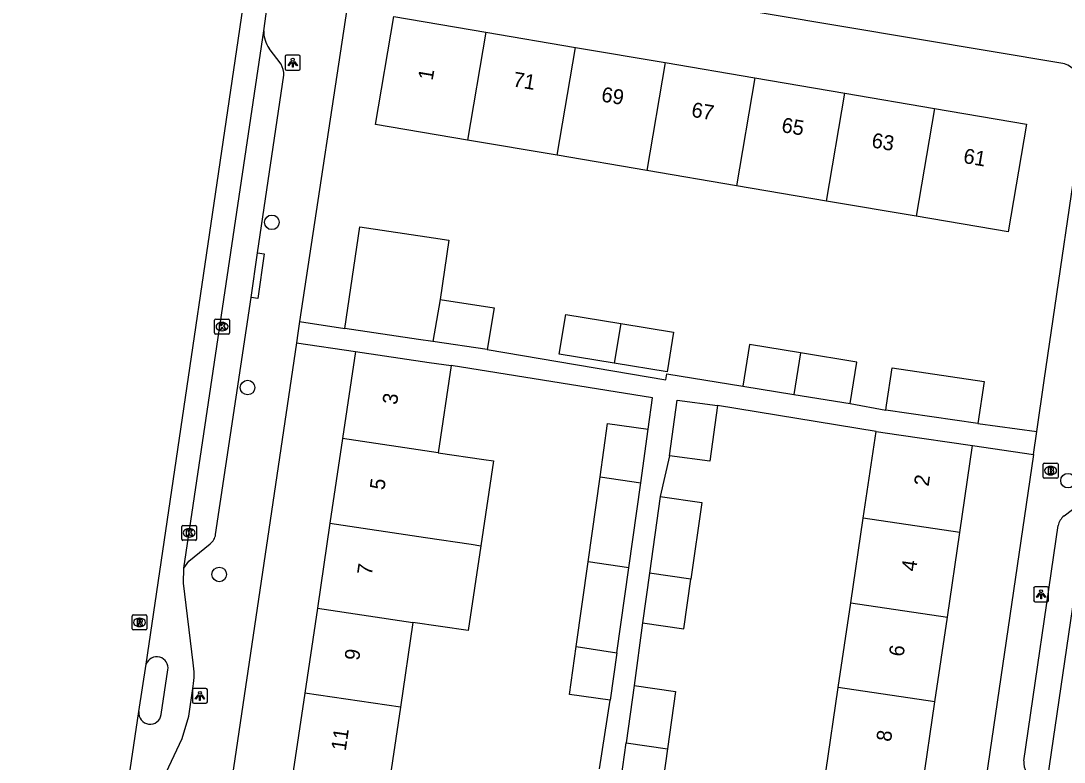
# Model space of a CAD drawing. Extents: x 163686 to 164493, y 382719 to 383870.
# Drawn here: x 163726.2 to 163796.1, y 383096.3 to 383145.9 of the extents above; entities that cross this region are included whole.
import ezdxf

# ---------------------------------------------------------------- set-up
doc = ezdxf.new("R2010")
doc.units = 0
for name, color, linetype in [('IMGEO_Boom', 7, 'Continuous'), ('IMGEO_Brandkraan', 7, 'Continuous'), ('IMGEO_Kolk', 7, 'Continuous'), ('IMGEO_Lichtpunt', 7, 'Continuous'), ('IMGEO_Pand', 7, 'Continuous'), ('IMGEO_Pand_nummerreeks', 7, 'Continuous'), ('IMGEO_Rijbaan_lokaal_open', 7, 'Continuous'), ('IMGEO_Rioolput', 7, 'Continuous'), ('IMGEO_Voetpad_open', 7, 'Continuous')]:
    doc.layers.add(name, color=color, linetype=linetype)

msp = doc.modelspace()

# ---------------------------------------------------------------- linework, layer by layer
at = {"layer": 'IMGEO_Boom'}
for centre in [(163743.043, 383132.436), (163741.413, 383121.365), (163796.388, 383115.13), (163739.516, 383108.846)]:
    msp.add_circle(centre, 0.489, dxfattribs=at)
at = {"layer": 'IMGEO_Brandkraan'}
for p, q in [((163794.721, 383115.373), (163794.721, 383116.225)), ((163794.796, 383116.299), (163795.648, 383116.299)), ((163795.722, 383116.225), (163795.722, 383115.373)), ((163795.232, 383115.519), (163795.207, 383115.519)), ((163795.209, 383116.079), (163795.234, 383116.079)), ((163795.648, 383115.299), (163794.796, 383115.299))]:
    msp.add_line(p, q, dxfattribs=at)
for points in [[(163794.721, 383115.373), (163794.721, 383116.225)], [(163794.796, 383116.299), (163795.648, 383116.299)], [(163795.722, 383116.225), (163795.722, 383115.373)], [(163795.069, 383115.999), (163795.069, 383115.599), (163795.282, 383115.599)], [(163795.3, 383115.999), (163795.069, 383115.999)], [(163795.248, 383115.918), (163795.194, 383115.918), (163795.194, 383115.842)], [(163795.194, 383115.842), (163795.247, 383115.842)], [(163795.256, 383115.766), (163795.194, 383115.766), (163795.194, 383115.685)], [(163795.194, 383115.685), (163795.256, 383115.685)], [(163795.648, 383115.299), (163794.796, 383115.299)]]:
    msp.add_lwpolyline(points, dxfattribs=at)
for centre, radius, start, end in [((163794.798, 383116.223), 0.0765, 91.55205, 178.44795), ((163794.798, 383116.223), 0.0765, 91.55205, 178.44795), ((163795.646, 383116.223), 0.0765, 1.55205, 88.44795), ((163795.646, 383116.223), 0.0765, 1.55205, 88.44795), ((163795.249, 383115.88), 0.0379, 267.82845, 90.93552), ((163795.257, 383115.725), 0.0404, 269.87594, 90.50774), ((163795.288, 383115.85), 0.251, 268.66757, 293.53466), ((163795.304, 383115.854), 0.145, 59.4692, 91.53667), ((163795.329, 383115.901), 0.0922, 285.51372, 58.15012), ((163795.334, 383115.709), 0.105, 301.31148, 78.98903), ((163794.798, 383115.375), 0.0765, 181.55205, 268.44795), ((163794.798, 383115.375), 0.0765, 181.55205, 268.44795), ((163795.646, 383115.375), 0.0765, 271.55205, 358.44795), ((163795.646, 383115.375), 0.0765, 271.55205, 358.44795)]:
    msp.add_arc(centre, radius, start, end, dxfattribs=at)
for centre, major_axis, ratio, start_param, end_param in [((163795.208, 383115.799), (-0.387, 0.002), 0.722429, 4.712389, 7.853982), ((163795.233, 383115.799), (-0.39, 0.002), 0.717154, 1.570796, 4.712389)]:
    msp.add_ellipse(centre, major_axis=major_axis, ratio=ratio, start_param=start_param, end_param=end_param, dxfattribs=at)
at = {"layer": 'IMGEO_Kolk'}
for p, q in [((163739.209, 383125.023), (163739.209, 383125.875)), ((163739.284, 383125.949), (163740.136, 383125.949)), ((163740.21, 383125.875), (163740.21, 383125.023)), ((163739.697, 383125.729), (163739.722, 383125.729)), ((163740.136, 383124.949), (163739.284, 383124.949)), ((163739.72, 383125.169), (163739.695, 383125.169)), ((163737.002, 383111.206), (163737.002, 383112.058)), ((163737.077, 383112.132), (163737.929, 383112.132)), ((163737.49, 383111.912), (163737.515, 383111.912)), ((163738.003, 383112.058), (163738.003, 383111.206)), ((163737.513, 383111.352), (163737.488, 383111.352)), ((163737.929, 383111.132), (163737.077, 383111.132))]:
    msp.add_line(p, q, dxfattribs=at)
for points in [[(163739.209, 383125.023), (163739.209, 383125.875)], [(163739.284, 383125.949), (163740.136, 383125.949)], [(163740.21, 383125.875), (163740.21, 383125.023)], [(163739.53, 383125.649), (163739.653, 383125.649), (163739.653, 383125.498), (163739.783, 383125.649), (163739.947, 383125.649), (163739.801, 383125.498), (163739.954, 383125.249), (163739.802, 383125.249), (163739.717, 383125.413), (163739.653, 383125.346), (163739.653, 383125.249), (163739.53, 383125.249), (163739.53, 383125.649)], [(163740.136, 383124.949), (163739.284, 383124.949)], [(163737.002, 383111.206), (163737.002, 383112.058)], [(163737.077, 383112.132), (163737.929, 383112.132)], [(163738.003, 383112.058), (163738.003, 383111.206)], [(163737.323, 383111.832), (163737.446, 383111.832), (163737.446, 383111.681), (163737.576, 383111.832), (163737.74, 383111.832), (163737.594, 383111.681), (163737.747, 383111.432), (163737.595, 383111.432), (163737.51, 383111.596), (163737.446, 383111.529), (163737.446, 383111.432), (163737.323, 383111.432), (163737.323, 383111.832)], [(163737.929, 383111.132), (163737.077, 383111.132)]]:
    msp.add_lwpolyline(points, dxfattribs=at)
for centre, start, end in [((163739.286, 383125.873), 91.55205, 178.44795), ((163739.286, 383125.873), 91.55205, 178.44795), ((163740.134, 383125.873), 1.55205, 88.44795), ((163740.134, 383125.873), 1.55205, 88.44795), ((163739.286, 383125.025), 181.55205, 268.44795), ((163739.286, 383125.025), 181.55205, 268.44795), ((163740.134, 383125.025), 271.55205, 358.44795), ((163740.134, 383125.025), 271.55205, 358.44795), ((163737.079, 383112.056), 91.55205, 178.44795), ((163737.079, 383112.056), 91.55205, 178.44795), ((163737.927, 383112.056), 1.55205, 88.44795), ((163737.927, 383112.056), 1.55205, 88.44795), ((163737.079, 383111.208), 181.55205, 268.44795), ((163737.079, 383111.208), 181.55205, 268.44795), ((163737.927, 383111.208), 271.55205, 358.44795), ((163737.927, 383111.208), 271.55205, 358.44795)]:
    msp.add_arc(centre, 0.0765, start, end, dxfattribs=at)
for centre, major_axis, ratio, start_param, end_param in [((163739.696, 383125.449), (-0.387, 0.002), 0.722429, 4.712389, 7.853982), ((163739.721, 383125.449), (-0.39, 0.002), 0.717154, 1.570796, 4.712389), ((163737.489, 383111.632), (-0.387, 0.002), 0.722429, 4.712389, 7.853982), ((163737.514, 383111.632), (-0.39, 0.002), 0.717154, 1.570796, 4.712389)]:
    msp.add_ellipse(centre, major_axis=major_axis, ratio=ratio, start_param=start_param, end_param=end_param, dxfattribs=at)
at = {"layer": 'IMGEO_Lichtpunt'}
for p, q in [((163743.941, 383143.537), (163743.941, 383142.73)), ((163743.941, 383143.537), (163743.941, 383142.73)), ((163744.843, 383143.632), (163744.035, 383143.632)), ((163744.843, 383143.632), (163744.035, 383143.632)), ((163744.937, 383142.73), (163744.937, 383143.537)), ((163744.937, 383142.73), (163744.937, 383143.537)), ((163744.035, 383142.636), (163744.843, 383142.636)), ((163744.035, 383142.636), (163744.843, 383142.636)), ((163794.088, 383107.922), (163794.088, 383107.115)), ((163794.088, 383107.922), (163794.088, 383107.115)), ((163794.99, 383108.017), (163794.182, 383108.017)), ((163794.99, 383108.017), (163794.182, 383108.017)), ((163795.084, 383107.115), (163795.084, 383107.922)), ((163795.084, 383107.115), (163795.084, 383107.922)), ((163794.182, 383107.021), (163794.99, 383107.021)), ((163794.182, 383107.021), (163794.99, 383107.021)), ((163737.726, 383101.118), (163737.726, 383100.311)), ((163737.726, 383101.118), (163737.726, 383100.311)), ((163738.628, 383101.213), (163737.82, 383101.213)), ((163738.628, 383101.213), (163737.82, 383101.213)), ((163738.722, 383100.311), (163738.722, 383101.118)), ((163738.722, 383100.311), (163738.722, 383101.118)), ((163737.82, 383100.217), (163738.628, 383100.217)), ((163737.82, 383100.217), (163738.628, 383100.217))]:
    msp.add_line(p, q, dxfattribs=at)
for points in [[(163744.315, 383143.201), (163744.354, 383143.173), (163744.166, 383142.911), (163744.128, 383142.938), (163744.315, 383143.201)], [(163744.417, 383143.153), (163744.464, 383143.153), (163744.464, 383142.831), (163744.417, 383142.831), (163744.417, 383143.153)], [(163744.527, 383143.173), (163744.565, 383143.2), (163744.752, 383142.938), (163744.713, 383142.91), (163744.527, 383143.173)], [(163794.462, 383107.586), (163794.501, 383107.558), (163794.313, 383107.296), (163794.275, 383107.323), (163794.462, 383107.586)], [(163794.564, 383107.538), (163794.611, 383107.538), (163794.611, 383107.216), (163794.564, 383107.216), (163794.564, 383107.538)], [(163794.674, 383107.558), (163794.712, 383107.585), (163794.899, 383107.323), (163794.86, 383107.295), (163794.674, 383107.558)], [(163738.1, 383100.782), (163738.139, 383100.754), (163737.951, 383100.492), (163737.913, 383100.519), (163738.1, 383100.782)], [(163738.202, 383100.734), (163738.249, 383100.734), (163738.249, 383100.412), (163738.202, 383100.412), (163738.202, 383100.734)], [(163738.312, 383100.754), (163738.35, 383100.781), (163738.537, 383100.519), (163738.498, 383100.491), (163738.312, 383100.754)]]:
    msp.add_lwpolyline(points, dxfattribs=at)
for centre in [(163744.44, 383143.335), (163794.587, 383107.72), (163738.225, 383100.916)]:
    msp.add_circle(centre, 0.0994, dxfattribs=at)
for centre, start, end in [((163744.035, 383143.537), 90, 180), ((163744.035, 383143.537), 90, 180), ((163744.843, 383143.537), 0, 90), ((163744.843, 383143.537), 0, 90), ((163744.035, 383142.73), 180, 270), ((163744.035, 383142.73), 180, 270), ((163744.843, 383142.73), 270, 0), ((163744.843, 383142.73), 270, 360), ((163794.182, 383107.922), 90, 180), ((163794.182, 383107.922), 90, 180), ((163794.99, 383107.922), 0, 90), ((163794.99, 383107.922), 0, 90), ((163794.182, 383107.115), 180, 270), ((163794.182, 383107.115), 180, 270), ((163794.99, 383107.115), 270, 0), ((163794.99, 383107.115), 270, 360), ((163737.82, 383101.118), 90, 180), ((163737.82, 383101.118), 90, 180), ((163738.628, 383101.118), 0, 90), ((163738.628, 383101.118), 0, 90), ((163737.82, 383100.311), 180, 270), ((163737.82, 383100.311), 180, 270), ((163738.628, 383100.311), 270, 0), ((163738.628, 383100.311), 270, 360)]:
    msp.add_arc(centre, 0.0946, start, end, dxfattribs=at)
at = {"layer": 'IMGEO_Pand'}
for points in [[(163756.151, 383137.95), (163749.991, 383138.997), (163751.219, 383146.224), (163757.382, 383145.176)], [(163757.382, 383145.176), (163756.151, 383137.95)], [(163757.382, 383145.176), (163763.393, 383144.155)], [(163762.162, 383136.928), (163763.393, 383144.155)], [(163763.393, 383144.155), (163769.405, 383143.133)], [(163769.405, 383143.133), (163768.175, 383135.906)], [(163769.405, 383143.133), (163775.416, 383142.111)], [(163775.416, 383142.111), (163774.186, 383134.884)], [(163775.416, 383142.111), (163781.428, 383141.089)], [(163780.198, 383133.862), (163781.428, 383141.089)], [(163781.428, 383141.089), (163787.44, 383140.067)], [(163787.44, 383140.067), (163793.599, 383139.02), (163792.37, 383131.793), (163786.21, 383132.84)], [(163787.44, 383140.067), (163786.21, 383132.84)], [(163762.162, 383136.928), (163756.151, 383137.95)], [(163768.175, 383135.906), (163762.162, 383136.928)], [(163774.186, 383134.884), (163768.175, 383135.906)], [(163780.198, 383133.862), (163774.186, 383134.884)], [(163786.21, 383132.84), (163780.198, 383133.862)], [(163747.926, 383125.324), (163748.934, 383132.13), (163753.881, 383131.397), (163754.891, 383131.248), (163754.319, 383127.255)], [(163754.319, 383127.255), (163753.829, 383124.45)], [(163754.319, 383127.255), (163757.947, 383126.718), (163757.472, 383123.911)], [(163765.979, 383123.004), (163762.302, 383123.605), (163762.736, 383126.261), (163766.431, 383125.657)], [(163753.829, 383124.45), (163752.873, 383124.592), (163747.926, 383125.324)], [(163766.431, 383125.657), (163769.961, 383125.08), (163769.527, 383122.424), (163765.979, 383123.004)], [(163766.431, 383125.657), (163765.979, 383123.004)], [(163748.645, 383123.788), (163747.781, 383117.957)], [(163748.645, 383123.788), (163753.592, 383123.056), (163755.049, 383122.84)], [(163757.472, 383123.911), (163753.829, 383124.45)], [(163778.468, 383123.695), (163775.052, 383124.253), (163774.597, 383121.466)], [(163778.468, 383123.695), (163778.013, 383120.908)], [(163781.789, 383120.292), (163782.244, 383123.079), (163778.468, 383123.695)], [(163755.049, 383122.84), (163754.185, 383117.005)], [(163784.189, 383119.855), (163784.237, 383120.178), (163784.607, 383122.688), (163790.76, 383121.781), (163790.342, 383118.948)], [(163774.597, 383121.466), (163778.013, 383120.908)], [(163769.683, 383116.795), (163770.191, 383120.523), (163772.901, 383120.154)], [(163778.013, 383120.908), (163781.789, 383120.292)], [(163772.901, 383120.154), (163772.393, 383116.426), (163769.683, 383116.795)], [(163790.342, 383118.948), (163784.189, 383119.855)], [(163765.042, 383115.39), (163765.543, 383118.953), (163768.267, 383118.57)], [(163767.762, 383114.985), (163768.267, 383118.57)], [(163782.666, 383112.612), (163783.524, 383118.428)], [(163783.524, 383118.428), (163785.052, 383118.203), (163789.998, 383117.474)], [(163747.781, 383117.957), (163746.939, 383112.272)], [(163754.185, 383117.005), (163747.781, 383117.957)], [(163754.185, 383117.005), (163757.237, 383116.551), (163757.885, 383116.455), (163757.048, 383110.769)], [(163789.14, 383111.657), (163789.998, 383117.474)], [(163764.241, 383109.7), (163765.042, 383115.39)], [(163765.042, 383115.39), (163767.762, 383114.985)], [(163766.962, 383109.296), (163767.762, 383114.985)], [(163769.06, 383114.059), (163768.339, 383108.933)], [(163769.06, 383114.059), (163771.845, 383113.668), (163771.121, 383108.523)], [(163781.83, 383106.943), (163782.666, 383112.612)], [(163789.14, 383111.657), (163782.666, 383112.612)], [(163746.939, 383112.272), (163746.097, 383106.587)], [(163746.939, 383112.272), (163753.343, 383111.32), (163756.392, 383110.867), (163757.048, 383110.769)], [(163788.304, 383105.988), (163789.14, 383111.657)], [(163757.048, 383110.769), (163756.203, 383105.085), (163752.501, 383105.635)], [(163763.441, 383104.009), (163764.241, 383109.7)], [(163766.962, 383109.296), (163764.241, 383109.7)], [(163766.162, 383103.604), (163766.962, 383109.296)], [(163768.339, 383108.933), (163767.87, 383105.601)], [(163767.87, 383105.601), (163770.655, 383105.209), (163771.121, 383108.523)], [(163771.121, 383108.523), (163768.339, 383108.933)], [(163746.097, 383106.587), (163745.255, 383100.902)], [(163746.097, 383106.587), (163752.501, 383105.635)], [(163780.994, 383101.273), (163781.83, 383106.943)], [(163781.83, 383106.943), (163788.304, 383105.988)], [(163752.501, 383105.635), (163751.659, 383099.95)], [(163787.468, 383100.318), (163788.304, 383105.988)], [(163765.714, 383100.424), (163762.99, 383100.807), (163763.441, 383104.009)], [(163763.441, 383104.009), (163766.162, 383103.604)], [(163766.162, 383103.604), (163765.714, 383100.424)], [(163745.255, 383100.902), (163744.413, 383095.217)], [(163751.659, 383099.95), (163745.255, 383100.902)], [(163767.326, 383101.402), (163766.788, 383097.575)], [(163767.326, 383101.402), (163770.088, 383101.013), (163769.547, 383097.168)], [(163780.158, 383095.603), (163780.994, 383101.273)], [(163787.468, 383100.318), (163780.994, 383101.273)], [(163786.632, 383094.648), (163787.468, 383100.318)], [(163751.659, 383099.95), (163750.817, 383094.265)], [(163766.335, 383094.355), (163766.788, 383097.575)], [(163766.788, 383097.575), (163769.547, 383097.168)], [(163769.547, 383097.168), (163769.097, 383093.966), (163766.335, 383094.355)]]:
    msp.add_lwpolyline(points, dxfattribs=at)
at = {"layer": 'IMGEO_Rijbaan_lokaal_open'}
for points in [[(163734.624, 383102.838), (163741.618, 383150.24)], [(163742.5, 383145.254), (163743.162, 383150.007)], [(163737.151, 383109.264), (163742.5, 383145.254)], [(163794.767, 383093.408), (163797.848, 383114.451)], [(163737.779, 383102.919), (163737.113, 383108.258), (163737.151, 383109.264)], [(163734.137, 383099.655), (163734.624, 383102.838)], [(163735.629, 383099.459), (163736.08, 383102.448)], [(163734.583, 383091.982), (163734.906, 383093.335), (163737.044, 383097.857), (163737.492, 383099.361), (163737.781, 383101.353)], [(163726.227, 383046.482), (163734.137, 383099.655)]]:
    msp.add_lwpolyline(points, dxfattribs=at)
for centre, radius, start, end in [((163735.333, 383102.572), 0.757, 350.6098, 159.40004), ((163732.023, 383102.129), 5.81, 352.32848, 7.81787), ((163734.884, 383099.566), 0.752, 173.20965, 351.82247)]:
    msp.add_arc(centre, radius, start, end, dxfattribs=at)
at = {"layer": 'IMGEO_Rioolput'}
for p, q in [((163733.674, 383105.21), (163733.674, 383106.062)), ((163733.749, 383106.136), (163734.601, 383106.136)), ((163734.162, 383105.916), (163734.187, 383105.916)), ((163734.675, 383106.062), (163734.675, 383105.21)), ((163734.601, 383105.136), (163733.749, 383105.136)), ((163734.185, 383105.356), (163734.16, 383105.356))]:
    msp.add_line(p, q, dxfattribs=at)
for points in [[(163733.674, 383105.21), (163733.674, 383106.062)], [(163733.749, 383106.136), (163734.601, 383106.136)], [(163734.263, 383105.834), (163734.011, 383105.836), (163734.011, 383105.436)], [(163734.189, 383105.755), (163734.135, 383105.755), (163734.135, 383105.674)], [(163734.135, 383105.674), (163734.187, 383105.674)], [(163734.675, 383106.062), (163734.675, 383105.21)], [(163734.601, 383105.136), (163733.749, 383105.136)], [(163734.011, 383105.436), (163734.135, 383105.436), (163734.135, 383105.598), (163734.146, 383105.598)], [(163734.193, 383105.569), (163734.264, 383105.436), (163734.404, 383105.436), (163734.339, 383105.562)]]:
    msp.add_lwpolyline(points, dxfattribs=at)
for centre, radius, start, end in [((163733.751, 383106.06), 0.0765, 91.55205, 178.44795), ((163733.751, 383106.06), 0.0765, 91.55205, 178.44795), ((163734.171, 383105.863), 0.19, 274.7715, 282.96867), ((163734.195, 383105.659), 0.0964, 77.00612, 93.18647), ((163734.209, 383105.716), 0.0378, 276.66336, 79.67722), ((163734.262, 383105.724), 0.109, 350.36119, 89.41601), ((163734.26, 383105.724), 0.112, 277.58423, 350.98172), ((163734.244, 383105.509), 0.108, 29.51342, 73.79051), ((163734.599, 383106.06), 0.0765, 1.55205, 88.44795), ((163734.599, 383106.06), 0.0765, 1.55205, 88.44795), ((163733.751, 383105.212), 0.0765, 181.55205, 268.44795), ((163733.751, 383105.212), 0.0765, 181.55205, 268.44795), ((163734.145, 383105.545), 0.0533, 26.02933, 88.69889), ((163734.599, 383105.212), 0.0765, 271.55205, 358.44795), ((163734.599, 383105.212), 0.0765, 271.55205, 358.44795)]:
    msp.add_arc(centre, radius, start, end, dxfattribs=at)
for centre, major_axis, ratio, start_param, end_param in [((163734.161, 383105.636), (-0.387, 0.002), 0.722429, 4.712389, 7.853982), ((163734.186, 383105.636), (-0.39, 0.002), 0.717154, 1.570796, 4.712389)]:
    msp.add_ellipse(centre, major_axis=major_axis, ratio=ratio, start_param=start_param, end_param=end_param, dxfattribs=at)
at = {"layer": 'IMGEO_Voetpad_open'}
for points in [[(163796.038, 383143.072), (163751.496, 383150.561), (163750.514, 383150.658)], [(163748.411, 383148.954), (163744.898, 383125.783)], [(163743.661, 383143.036), (163742.863, 383144.092)], [(163742.093, 383130.393), (163743.851, 383142.286)], [(163794.3, 383118.433), (163794.798, 383121.842), (163797.575, 383140.863)], [(163741.648, 383127.399), (163742.093, 383130.393)], [(163742.093, 383130.393), (163742.533, 383130.334), (163742.095, 383127.338), (163741.648, 383127.399)], [(163739.278, 383111.53), (163741.648, 383127.399)], [(163744.898, 383125.783), (163744.782, 383125.016), (163744.687, 383124.374)], [(163744.898, 383125.783), (163747.926, 383125.324)], [(163744.687, 383124.374), (163735.38, 383061.541)], [(163744.687, 383124.374), (163748.645, 383123.788)], [(163757.472, 383123.911), (163769.436, 383121.886), (163769.505, 383122.297), (163774.597, 383121.466)], [(163768.267, 383118.57), (163768.554, 383120.679), (163755.049, 383122.84)], [(163781.789, 383120.292), (163784.189, 383119.855)], [(163783.524, 383118.428), (163772.901, 383120.154)], [(163790.342, 383118.948), (163794.3, 383118.433)], [(163794.072, 383116.877), (163794.3, 383118.433)], [(163769.683, 383116.795), (163769.06, 383114.059)], [(163794.072, 383116.877), (163787.38, 383071.224)], [(163789.998, 383117.474), (163794.072, 383116.877)], [(163796.129, 383112.765), (163797.169, 383113.546)], [(163793.426, 383096.349), (163795.729, 383112.115)], [(163737.471, 383109.738), (163738.907, 383110.895)], [(163737.151, 383109.264), (163737.471, 383109.738)], [(163767.87, 383105.601), (163767.326, 383101.402)], [(163765.001, 383095.815), (163765.714, 383100.424)]]:
    msp.add_lwpolyline(points, dxfattribs=at)
for centre, radius, start, end in [((163744.4, 383145.21), 1.901, 178.67062, 216.02619), ((163742.377, 383142.312), 1.474, 359.00273, 29.42897), ((163795.795, 383141.798), 1.297, 37.13073, 79.21078), ((163796.709, 383111.96), 0.992, 125.77263, 171.01236), ((163738.291, 383111.681), 0.999, 308.10425, 351.30437), ((163794.684, 383096.257), 1.262, 175.83274, 210.92434)]:
    msp.add_arc(centre, radius, start, end, dxfattribs=at)

# ---------------------------------------------------------------- texts
at = {"layer": 'IMGEO_Pand_nummerreeks'}
for s, rotation, p in [('1', 80.3565, (163753.812, 383141.902)), ('71', 350.35274, (163759.147, 383141.549)), ('69', 350.35274, (163765.071, 383140.542)), ('67', 350.35274, (163771.107, 383139.516)), ('65', 350.35274, (163777.143, 383138.49)), ('63', 350.35274, (163783.18, 383137.464)), ('61', 350.35274, (163789.328, 383136.419)), ('3', 81.57534, (163751.426, 383120.179)), ('2', 81.61175, (163787.044, 383114.714)), ('5', 81.57773, (163750.581, 383114.467)), ('7', 81.57773, (163749.735, 383108.755)), ('4', 81.61175, (163786.203, 383109.01)), ('9', 81.57534, (163748.888, 383103.043)), ('6', 81.61175, (163785.362, 383103.304)), ('11', 81.57534, (163747.992, 383096.989)), ('8', 81.61175, (163784.521, 383097.602))]:
    msp.add_text(s, height=1, rotation=rotation, dxfattribs=at).set_placement(p)

doc.saveas('drawing.dxf')
